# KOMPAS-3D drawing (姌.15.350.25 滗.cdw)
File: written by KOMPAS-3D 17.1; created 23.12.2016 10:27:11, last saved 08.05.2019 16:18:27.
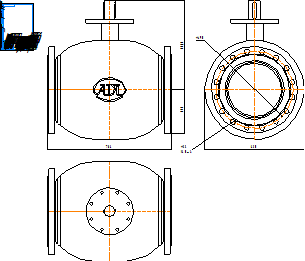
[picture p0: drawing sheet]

Sheet 1: A4, portrait

Title block, sheet 1: name: КШ.15.350.25 фф; material: Внимание! Данный продукт является объектом авторского права ООО «Торговый Дом АДЛ». / Запрещается изменение, копирование, распространение / (в том числе путем копирования на другие сайты и ресурсы в Интернете) / или любое иное использование информации и объектов без предварительного / согласия правообладателя (ООО «Торговый Дом АДЛ»).; sheets: 1; organisation: ООО "Торговый дом АДЛ"; sheet format: A4; stored path: C:\Users\tra\Desktop\2д чертежи\Шаровые краны БИВАЛ\КШ_Бивал_серия_14_15\KOMPAS_2D\КШ.15.350.25 фф.cdw

Views: Вид 1, Проекционный вид 2, Проекционный вид 3
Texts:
  Klimkovich
  ADL
Dimensions and other numbers on the sheet: 786; 564,5; 275; 630; 490; 33; 16 Отв.; 1:1; 1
